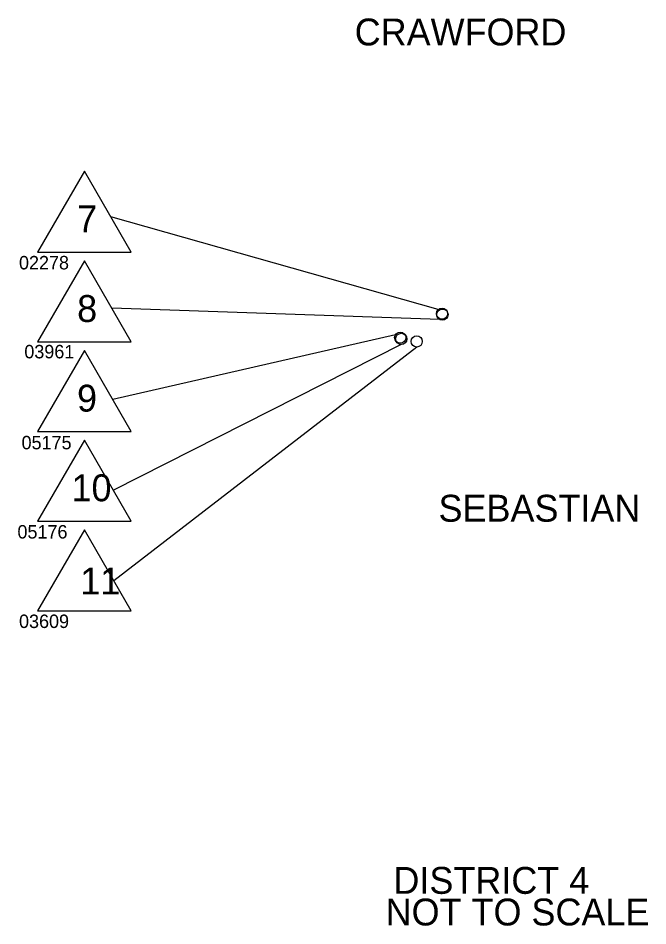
# Model space of a CAD drawing. Extents: x -35254 to 17396, y -8913 to 11592.
# Drawn here: x -14100 to -8481, y -7049 to 1051 of the extents above; entities that cross this region are included whole.
import ezdxf

# ---------------------------------------------------------------- set-up
doc = ezdxf.new("R2010")
doc.units = 0
for name, color, linetype in [('2', 7, 'Continuous'), ('R_Annotation', 7, 'Continuous'), ('R_No Plot', 7, 'Continuous')]:
    doc.layers.add(name, color=color, linetype=linetype)

msp = doc.modelspace()

# ---------------------------------------------------------------- linework, layer by layer
at = {"layer": 'R_Annotation'}
for p, q in [((-13508.5, -313.7), (-13926.4, -1037.6)), ((-13090.5, -1037.6), (-13508.5, -313.7)), ((-10351.2, -1549.5), (-13273.4, -720.9)), ((-13926.4, -1037.6), (-13090.5, -1037.6)), ((-13508.5, -1113.7), (-13926.4, -1837.6)), ((-13090.5, -1837.6), (-13508.5, -1113.7)), ((-10337.2, -1637.4), (-13263.4, -1538.1)), ((-10731.5, -1775.3), (-13255.7, -2351.4)), ((-13926.4, -1837.6), (-13090.5, -1837.6)), ((-10681.5, -1861), (-13249.5, -3162.2)), ((-13508.5, -1913.7), (-13926.4, -2637.6)), ((-13090.5, -2637.6), (-13508.5, -1913.7)), ((-10543.3, -1883.8), (-13244.9, -3970.2)), ((-13926.4, -2637.6), (-13090.5, -2637.6)), ((-13508.5, -2713.7), (-13926.4, -3437.6)), ((-13090.5, -3437.6), (-13508.5, -2713.7)), ((-13926.4, -3437.6), (-13090.5, -3437.6)), ((-13508.5, -3513.7), (-13926.4, -4237.6)), ((-13090.5, -4237.6), (-13508.5, -3513.7)), ((-13926.4, -4237.6), (-13090.5, -4237.6))]:
    msp.add_line(p, q, dxfattribs=at)
for centre in [(-10317.2, -1586.1), (-10313.6, -1594.3), (-10690.7, -1799.8), (-10681.5, -1811), (-10543.3, -1833.8)]:
    msp.add_circle(centre, 50, dxfattribs=at)

# ---------------------------------------------------------------- texts
at = {"layer": '2'}
for s, p in [('CRAWFORD', (-11097, 807.8)), ('SEBASTIAN', (-10348.7, -3442.2)), ('NOT TO SCALE', (-10820.9, -7045.5))]:
    msp.add_text(s, height=240, dxfattribs=at).set_placement(p)
at = {"layer": 'R_Annotation'}
for s, p in [('7', (-13573.8, -860)), ('8', (-13573.8, -1660)), ('9', (-13574.7, -2460)), ('10', (-13623.9, -3260)), ('11', (-13545.4, -4091.5)), ('DISTRICT 4', (-10751.1, -6763.2))]:
    msp.add_text(s, height=240, dxfattribs=at).set_placement(p)
at = {"layer": 'R_No Plot'}
for s, p in [('02278', (-14092.8, -1190.8)), ('03961', (-14045.1, -1984.6)), ('05175', (-14069.8, -2796.4)), ('05176', (-14106.5, -3592.4)), ('03609', (-14092.4, -4391.1))]:
    msp.add_text(s, height=120, dxfattribs=at).set_placement(p)

doc.saveas('drawing.dxf')
